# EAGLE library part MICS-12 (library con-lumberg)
CONNECTOR
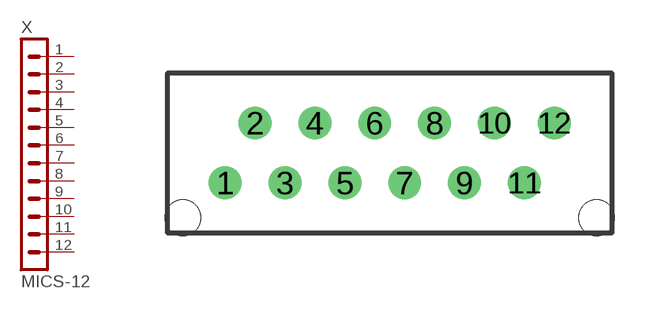
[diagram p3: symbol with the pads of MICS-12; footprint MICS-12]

Designator prefix X

## MICS-12 (OC_FARNELL: 808910; OC_NEWARK: unknown)  [MICS-12]
1  1  pas
2  2  pas
3  3  pas
4  4  pas
5  5  pas
6  6  pas
7  7  pas
8  8  pas
9  9  pas
10  10  pas
11  11  pas
12  12  pas

## Footprint MICS-12 (pad centres in mm)
CONNECTOR
drill 0.85 pad 1.397 round: 1 -6.985,-1.27; 2 -5.715,1.27; 3 -4.445,-1.27; 4 -3.175,1.27; 5 -1.905,-1.27; 6 -0.635,1.27; 7 0.635,-1.27; 8 1.905,1.27; 9 3.175,-1.27; 10 4.445,1.27; 11 5.715,-1.27; 12 6.985,1.27
hole 1.5 at 8.785,-2.75
hole 1.5 at -8.785,-2.75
